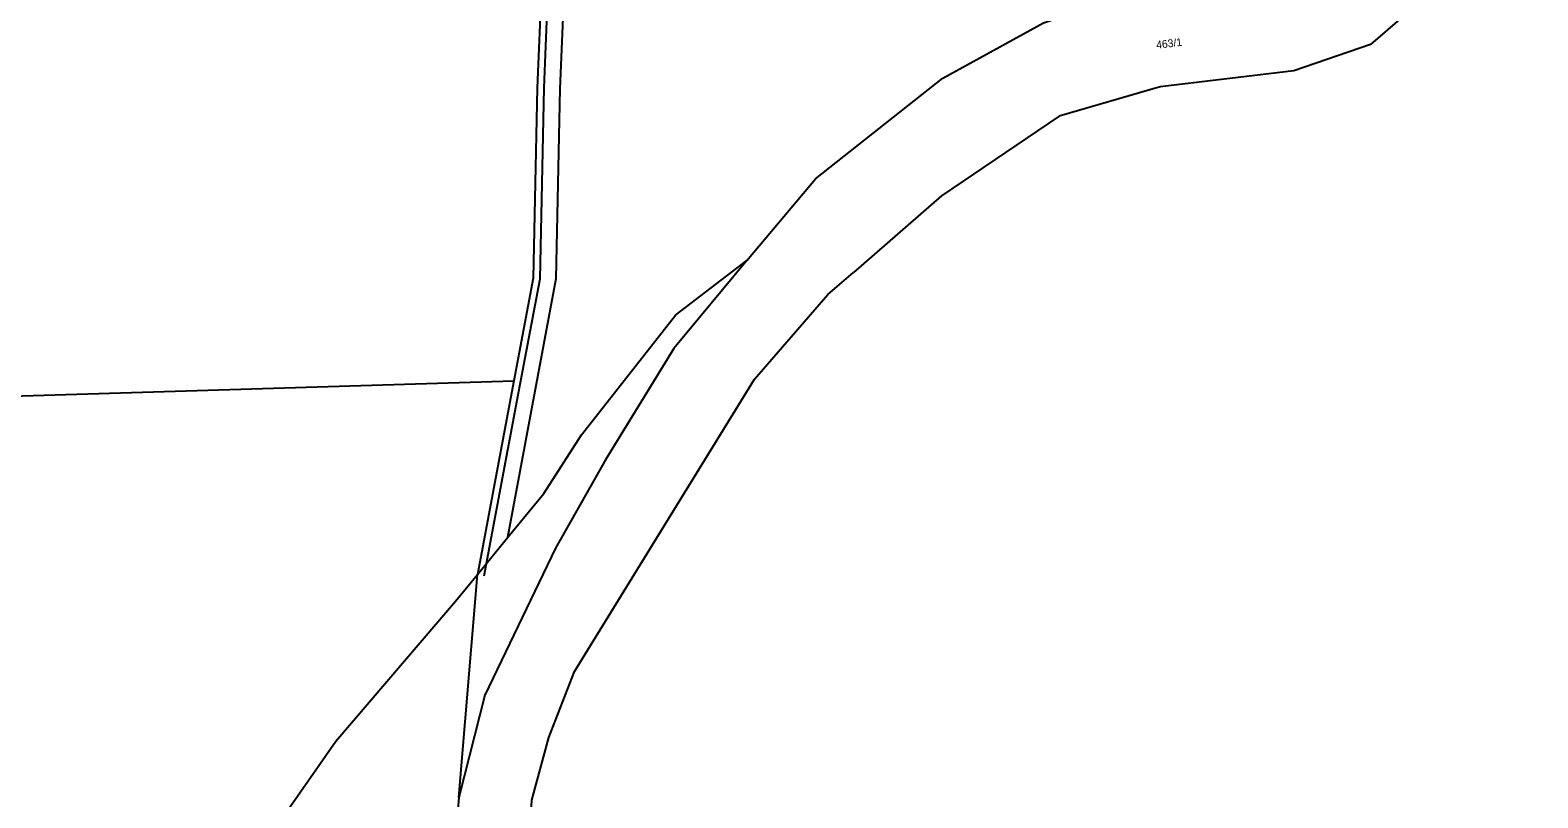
# Model space of a CAD drawing. Extents: x -882150 to -879379, y -1022570 to -1019819.
# Drawn here: x -880638.1 to -880308.9, y -1022063.9 to -1021896.3 of the extents above; entities that cross this region are included whole.
import ezdxf

# ---------------------------------------------------------------- set-up
doc = ezdxf.new("R2010")
doc.units = 0
for name, color, linetype in [('Hranice parcel', 7, 'Continuous'), ('Parcelní čísla', 7, 'Continuous'), ('Vnitřní kresba', 7, 'Continuous')]:
    doc.layers.add(name, color=color, linetype=linetype)

msp = doc.modelspace()

# ---------------------------------------------------------------- linework, layer by layer
at = {"layer": 'Hranice parcel'}
for p, q in [((-880532.51, -1021972.91), (-880540.47, -1022015.14)), ((-880540.47, -1022015.14), (-880533.86, -1022007.05))]:
    msp.add_line(p, q, dxfattribs=at)
for points in [[(-880533.86, -1022007.05), (-880523.29, -1021950.58), (-880522.43, -1021909.12), (-880520.53, -1021864.27), (-880518.3, -1021819.45), (-880460.57, -1021640.65), (-880455.51, -1021609.22), (-880454.71, -1021579.75), (-880473.1, -1021460.72)], [(-880505.13, -1021762.84), (-880523.29, -1021819.2), (-880525.52, -1021864.02), (-880527.43, -1021908.91), (-880528.29, -1021950.47), (-880532.51, -1021972.91)], [(-880308.92, -1021866.24), (-880316.75, -1021874.64), (-880345.49, -1021899.44), (-880362.19, -1021905.21), (-880391.36, -1021908.72), (-880413.46, -1021915.14), (-880439.14, -1021932.52), (-880458.37, -1021949.23)], [(-880481.62, -1021946.61), (-880466.63, -1021928.82), (-880438.87, -1021906.81), (-880416.85, -1021894.75), (-880393.19, -1021886.89)], [(-880901.81, -1021901.82), (-880909.52, -1021984.44), (-880721.02, -1021978.67), (-880532.51, -1021972.91)], [(-880481.62, -1021946.61), (-880497.56, -1021965.83), (-880512.49, -1021990.16), (-880523.44, -1022009.43), (-880538.87, -1022041.47), (-880544.54, -1022063.85), (-880547.35, -1022097.08), (-880546.45, -1022128.98), (-880547.31, -1022165.35)], [(-880533.86, -1022007.05), (-880526.01, -1021997.45), (-880517.76, -1021984.7), (-880497.25, -1021958.56), (-880481.62, -1021946.61)], [(-880438.9, -1022312.23), (-880448.03, -1022299.45), (-880455.75, -1022284.78), (-880487.48, -1022243.34), (-880524.79, -1022153.92), (-880529.34, -1022124.84), (-880530.7, -1022098.83), (-880528.56, -1022064.4), (-880524.89, -1022050.76), (-880519.28, -1022036.32), (-880479.95, -1021972.5), (-880463.94, -1021954.07), (-880458.37, -1021949.23)], [(-880731.91, -1022394.96), (-880696.51, -1022334.22), (-880675.29, -1022301.87), (-880657.9, -1022264.58), (-880644.21, -1022212.25), (-880627.87, -1022157.84), (-880621.99, -1022143.56), (-880585.18, -1022071.28), (-880571.42, -1022051.57), (-880545.28, -1022021.02), (-880540.47, -1022015.14)]]:
    msp.add_lwpolyline(points, dxfattribs=at)
at = {"layer": 'Vnitřní kresba'}
for p, q in [((-880525.93, -1021908.96), (-880524.02, -1021864.02)), ((-880526.79, -1021950.62), (-880525.93, -1021908.96)), ((-880531.11, -1021973.6), (-880526.79, -1021950.62)), ((-880539, -1022015.42), (-880531.11, -1021973.6)), ((-880544.54, -1022063.85), (-880540.47, -1022015.14))]:
    msp.add_line(p, q, dxfattribs=at)

# ---------------------------------------------------------------- texts
at = {"layer": 'Parcelní čísla'}
msp.add_text('463/1', height=1.7, rotation=7, dxfattribs=at).set_placement((-880392.156, -1021900.423))

doc.saveas('drawing.dxf')
